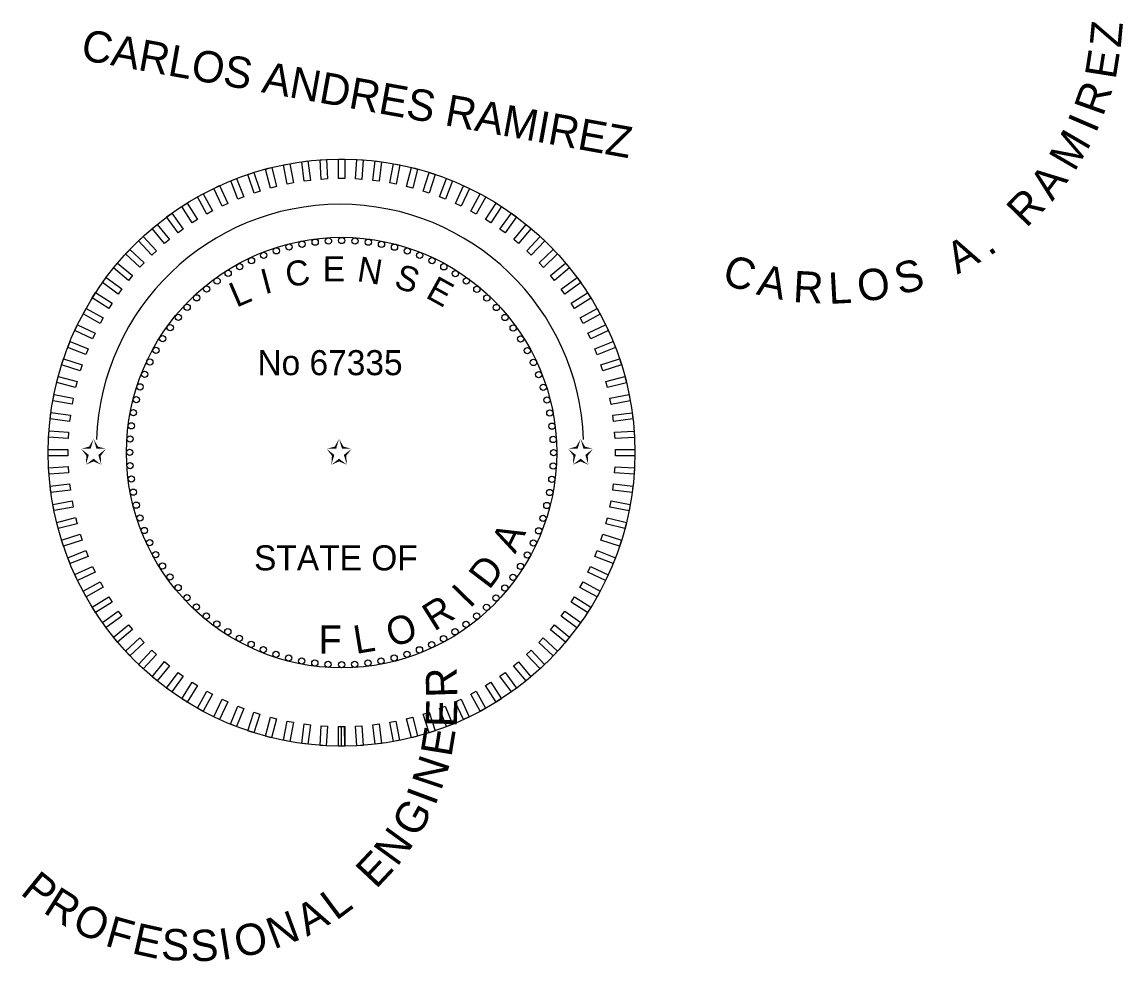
# Model space of a CAD drawing. Extents: x -0.86 to 1.33, y -1.26 to 1.83.
# Drawn here: x -0.5531 to -0.2599, y 0.6499 to 0.9 of the extents above; entities that cross this region are included whole.
import ezdxf

# ---------------------------------------------------------------- set-up
doc = ezdxf.new("R2010")
doc.units = 0
for name, color, linetype in [('Default', 7, 'Continuous'), ('FLMap1', 7, 'Continuous'), ('FLMap3', 7, 'Continuous'), ('TextMisc', 7, 'Continuous')]:
    doc.layers.add(name, color=color, linetype=linetype)

msp = doc.modelspace()

# ---------------------------------------------------------------- linework, layer by layer
at = {"layer": 'Default'}
msp.add_arc((-0.46841, 0.78662), 0.06487, 2.0456, 177.9544, dxfattribs=at)
at = {"layer": 'FLMap1'}
for radius in [0.07809, 0.05727]:
    msp.add_circle((-0.46797, 0.78544), radius, dxfattribs=at)
at = {"layer": 'FLMap3'}
for p, q in [((-0.46881, 0.70734), (-0.46882, 0.71255)), ((-0.46797, 0.70734), (-0.46799, 0.71255)), ((-0.46714, 0.70735), (-0.46716, 0.71255))]:
    msp.add_line(p, q, dxfattribs=at)
for points in [[(-0.4808, 0.8572), (-0.48245, 0.85688), (-0.48342, 0.86199), (-0.48177, 0.8623)], [(-0.47627, 0.85786), (-0.47794, 0.85765), (-0.47859, 0.86281), (-0.47692, 0.86302)], [(-0.4717, 0.85824), (-0.47338, 0.85813), (-0.47371, 0.86332), (-0.47203, 0.86343)], [(-0.46713, 0.85833), (-0.46881, 0.85833), (-0.46881, 0.86353), (-0.46713, 0.86353)], [(-0.46255, 0.85813), (-0.46423, 0.85824), (-0.4639, 0.86343), (-0.46222, 0.86332)], [(-0.458, 0.85765), (-0.45966, 0.85786), (-0.45901, 0.86302), (-0.45734, 0.86281)], [(-0.45348, 0.85688), (-0.45513, 0.85719), (-0.45416, 0.8623), (-0.45251, 0.86199)], [(-0.48969, 0.85502), (-0.49129, 0.8545), (-0.4929, 0.85945), (-0.4913, 0.85997)], [(-0.48528, 0.85625), (-0.48691, 0.85583), (-0.4882, 0.86087), (-0.48657, 0.86129)], [(-0.44902, 0.85583), (-0.45065, 0.85624), (-0.44936, 0.86128), (-0.44773, 0.86086)], [(-0.44464, 0.8545), (-0.44624, 0.85502), (-0.44463, 0.85996), (-0.44304, 0.85944)], [(-0.49824, 0.85175), (-0.49976, 0.85104), (-0.50198, 0.85574), (-0.50046, 0.85646)], [(-0.49402, 0.85352), (-0.49558, 0.8529), (-0.4975, 0.85774), (-0.49593, 0.85836)], [(-0.44035, 0.8529), (-0.44192, 0.85352), (-0.44, 0.85835), (-0.43844, 0.85773)], [(-0.43617, 0.85103), (-0.43769, 0.85175), (-0.43548, 0.85645), (-0.43396, 0.85574)], [(-0.50235, 0.84972), (-0.50382, 0.84891), (-0.50632, 0.85347), (-0.50485, 0.85428)], [(-0.43211, 0.8489), (-0.43359, 0.84971), (-0.43108, 0.85427), (-0.42961, 0.85346)], [(-0.50631, 0.84744), (-0.50773, 0.84653), (-0.51052, 0.85093), (-0.5091, 0.85183)], [(-0.4282, 0.84653), (-0.42962, 0.84743), (-0.42683, 0.85182), (-0.42541, 0.85092)], [(-0.51013, 0.84491), (-0.51149, 0.84392), (-0.51455, 0.84813), (-0.51319, 0.84911)], [(-0.42444, 0.84391), (-0.4258, 0.8449), (-0.42275, 0.8491), (-0.42139, 0.84812)], [(-0.51378, 0.84214), (-0.51508, 0.84107), (-0.51839, 0.84508), (-0.5171, 0.84615)], [(-0.42086, 0.84106), (-0.42215, 0.84213), (-0.41884, 0.84614), (-0.41754, 0.84507)], [(-0.51725, 0.83915), (-0.51848, 0.838), (-0.52204, 0.84179), (-0.52081, 0.84294)], [(-0.41746, 0.83799), (-0.41868, 0.83914), (-0.41512, 0.84293), (-0.4139, 0.84178)], [(-0.52053, 0.83595), (-0.52168, 0.83473), (-0.52547, 0.83829), (-0.52432, 0.83951)], [(-0.41426, 0.83472), (-0.41541, 0.83594), (-0.41162, 0.8395), (-0.41047, 0.83828)], [(-0.5236, 0.83255), (-0.52467, 0.83126), (-0.52867, 0.83457), (-0.5276, 0.83587)], [(-0.41127, 0.83125), (-0.41234, 0.83254), (-0.40833, 0.83586), (-0.40726, 0.83456)], [(-0.52644, 0.82897), (-0.52743, 0.82761), (-0.53164, 0.83066), (-0.53065, 0.83202)], [(-0.40851, 0.82759), (-0.40949, 0.82896), (-0.40529, 0.83201), (-0.4043, 0.83065)], [(-0.52906, 0.82521), (-0.52996, 0.82379), (-0.53435, 0.82658), (-0.53345, 0.828)], [(-0.40598, 0.82378), (-0.40688, 0.8252), (-0.40249, 0.82798), (-0.40158, 0.82656)], [(-0.53144, 0.8213), (-0.53225, 0.81982), (-0.53681, 0.82233), (-0.536, 0.8238)], [(-0.40369, 0.81981), (-0.4045, 0.82128), (-0.39994, 0.82379), (-0.39913, 0.82231)], [(-0.53357, 0.81724), (-0.53428, 0.81572), (-0.53899, 0.81793), (-0.53827, 0.81946)], [(-0.40166, 0.8157), (-0.40238, 0.81723), (-0.39767, 0.81944), (-0.39695, 0.81792)], [(-0.53543, 0.81306), (-0.53605, 0.8115), (-0.54089, 0.81341), (-0.54027, 0.81497)], [(-0.39989, 0.81148), (-0.40051, 0.81304), (-0.39567, 0.81496), (-0.39505, 0.8134)], [(-0.53703, 0.80877), (-0.53755, 0.80717), (-0.5425, 0.80878), (-0.54198, 0.81038)], [(-0.39839, 0.80715), (-0.39891, 0.80875), (-0.39396, 0.81036), (-0.39344, 0.80876)], [(-0.53836, 0.80439), (-0.53878, 0.80276), (-0.54382, 0.80405), (-0.5434, 0.80568)], [(-0.39716, 0.80274), (-0.39758, 0.80437), (-0.39254, 0.80566), (-0.39212, 0.80404)], [(-0.53941, 0.79993), (-0.53973, 0.79828), (-0.54484, 0.79925), (-0.54452, 0.8009)], [(-0.39622, 0.79826), (-0.39653, 0.79991), (-0.39142, 0.80089), (-0.39111, 0.79924)], [(-0.54018, 0.79541), (-0.54039, 0.79375), (-0.54555, 0.7944), (-0.54534, 0.79607)], [(-0.39555, 0.79373), (-0.39576, 0.7954), (-0.3906, 0.79605), (-0.39039, 0.79438)], [(-0.54067, 0.79086), (-0.54077, 0.78918), (-0.54596, 0.78951), (-0.54586, 0.79119)], [(-0.39517, 0.78917), (-0.39528, 0.79085), (-0.39009, 0.79117), (-0.38998, 0.78949)], [(-0.54086, 0.78629), (-0.54086, 0.7846), (-0.54606, 0.7846), (-0.54606, 0.78629)], [(-0.39508, 0.78459), (-0.39508, 0.78627), (-0.38988, 0.78627), (-0.38988, 0.78459)], [(-0.54077, 0.78171), (-0.54067, 0.78003), (-0.54586, 0.7797), (-0.54596, 0.78138)], [(-0.39528, 0.78001), (-0.39518, 0.78169), (-0.38998, 0.78137), (-0.39009, 0.77969)], [(-0.5404, 0.77714), (-0.54018, 0.77548), (-0.54534, 0.77482), (-0.54556, 0.77649)], [(-0.39576, 0.77546), (-0.39555, 0.77713), (-0.39039, 0.77648), (-0.3906, 0.77481)], [(-0.53973, 0.77261), (-0.53942, 0.77096), (-0.54453, 0.76999), (-0.54484, 0.77164)], [(-0.39653, 0.77095), (-0.39622, 0.7726), (-0.39111, 0.77162), (-0.39142, 0.76997)], [(-0.53878, 0.76813), (-0.53837, 0.7665), (-0.5434, 0.76521), (-0.54382, 0.76684)], [(-0.39758, 0.76649), (-0.39717, 0.76812), (-0.39213, 0.76682), (-0.39255, 0.7652)], [(-0.53756, 0.76372), (-0.53704, 0.76212), (-0.54199, 0.76051), (-0.5425, 0.76211)], [(-0.39891, 0.76211), (-0.39839, 0.76371), (-0.39345, 0.7621), (-0.39397, 0.7605)], [(-0.53606, 0.75939), (-0.53544, 0.75783), (-0.54027, 0.75592), (-0.54089, 0.75748)], [(-0.40051, 0.75782), (-0.3999, 0.75938), (-0.39506, 0.75746), (-0.39568, 0.7559)], [(-0.53429, 0.75517), (-0.53357, 0.75365), (-0.53828, 0.75143), (-0.53899, 0.75296)], [(-0.40238, 0.75363), (-0.40167, 0.75516), (-0.39696, 0.75294), (-0.39768, 0.75142)], [(-0.53226, 0.75107), (-0.53145, 0.74959), (-0.536, 0.74709), (-0.53681, 0.74856)], [(-0.40451, 0.74958), (-0.4037, 0.75105), (-0.39914, 0.74855), (-0.39995, 0.74707)], [(-0.52997, 0.7471), (-0.52907, 0.74568), (-0.53346, 0.74289), (-0.53436, 0.74431)], [(-0.40689, 0.74566), (-0.40598, 0.74708), (-0.40159, 0.7443), (-0.40249, 0.74288)], [(-0.52744, 0.74328), (-0.52645, 0.74192), (-0.53066, 0.73886), (-0.53165, 0.74022)], [(-0.4095, 0.74191), (-0.40851, 0.74327), (-0.40431, 0.74021), (-0.4053, 0.73885)], [(-0.52468, 0.73963), (-0.52361, 0.73833), (-0.52761, 0.73502), (-0.52868, 0.73631)], [(-0.41235, 0.73832), (-0.41128, 0.73962), (-0.40727, 0.7363), (-0.40834, 0.73501)], [(-0.52169, 0.73616), (-0.52054, 0.73493), (-0.52433, 0.73137), (-0.52548, 0.7326)], [(-0.41542, 0.73492), (-0.41427, 0.73615), (-0.41048, 0.73259), (-0.41163, 0.73136)], [(-0.51849, 0.73288), (-0.51726, 0.73173), (-0.52082, 0.72794), (-0.52205, 0.72909)], [(-0.4187, 0.73172), (-0.41747, 0.73287), (-0.41391, 0.72908), (-0.41513, 0.72793)], [(-0.51509, 0.72982), (-0.51379, 0.72874), (-0.51711, 0.72474), (-0.5184, 0.72581)], [(-0.5115, 0.72697), (-0.51014, 0.72598), (-0.5132, 0.72177), (-0.51456, 0.72276)], [(-0.42582, 0.72597), (-0.42446, 0.72696), (-0.4214, 0.72275), (-0.42276, 0.72176)], [(-0.42217, 0.72873), (-0.42087, 0.72981), (-0.41755, 0.7258), (-0.41885, 0.72473)], [(-0.50775, 0.72435), (-0.50633, 0.72345), (-0.50911, 0.71906), (-0.51053, 0.71996)], [(-0.42963, 0.72344), (-0.42821, 0.72434), (-0.42543, 0.71995), (-0.42685, 0.71905)], [(-0.50383, 0.72197), (-0.50236, 0.72116), (-0.50486, 0.7166), (-0.50634, 0.71741)], [(-0.4336, 0.72115), (-0.43213, 0.72196), (-0.42962, 0.71741), (-0.4311, 0.7166)], [(-0.49978, 0.71985), (-0.49825, 0.71913), (-0.50047, 0.71442), (-0.50199, 0.71514)], [(-0.43771, 0.71912), (-0.43618, 0.71984), (-0.43397, 0.71513), (-0.43549, 0.71442)], [(-0.4956, 0.71798), (-0.49403, 0.71736), (-0.49595, 0.71252), (-0.49751, 0.71314)], [(-0.4913, 0.71638), (-0.48971, 0.71586), (-0.49131, 0.71091), (-0.49291, 0.71143)], [(-0.44626, 0.71585), (-0.44466, 0.71637), (-0.44305, 0.71143), (-0.44465, 0.71091)], [(-0.44193, 0.71735), (-0.44037, 0.71797), (-0.43845, 0.71314), (-0.44002, 0.71252)], [(-0.48692, 0.71505), (-0.48529, 0.71463), (-0.48659, 0.70959), (-0.48822, 0.71001)], [(-0.48247, 0.714), (-0.48081, 0.71368), (-0.48179, 0.70857), (-0.48344, 0.70889)], [(-0.47795, 0.71323), (-0.47628, 0.71302), (-0.47693, 0.70786), (-0.4786, 0.70807)], [(-0.4734, 0.71274), (-0.47172, 0.71264), (-0.47205, 0.70745), (-0.47372, 0.70755)], [(-0.46882, 0.71255), (-0.46714, 0.71255), (-0.46714, 0.70735), (-0.46882, 0.70735)], [(-0.46424, 0.71264), (-0.46257, 0.71274), (-0.46224, 0.70755), (-0.46392, 0.70745)], [(-0.45968, 0.71302), (-0.45801, 0.71323), (-0.45736, 0.70807), (-0.45903, 0.70786)], [(-0.45515, 0.71368), (-0.4535, 0.71399), (-0.45252, 0.70889), (-0.45417, 0.70857)], [(-0.45067, 0.71463), (-0.44904, 0.71504), (-0.44775, 0.71001), (-0.44937, 0.70959)]]:
    msp.add_lwpolyline(points, close=True, dxfattribs=at)
for centre in [(-0.4785, 0.84088), (-0.475, 0.84143), (-0.47147, 0.84176), (-0.46793, 0.84187), (-0.46438, 0.84176), (-0.46085, 0.84142), (-0.45735, 0.84086), (-0.4887, 0.83793), (-0.48537, 0.83912), (-0.48196, 0.84011), (-0.45389, 0.84009), (-0.45049, 0.83909), (-0.44716, 0.83789), (-0.49512, 0.83491), (-0.49196, 0.83652), (-0.4439, 0.83648), (-0.44075, 0.83487), (-0.49817, 0.83311), (-0.4377, 0.83306), (-0.50391, 0.82895), (-0.50111, 0.83112), (-0.43477, 0.83107), (-0.43197, 0.82889), (-0.50657, 0.82661), (-0.42931, 0.82654), (-0.50908, 0.8241), (-0.4268, 0.82403), (-0.51143, 0.82145), (-0.42446, 0.82137), (-0.5136, 0.81865), (-0.42229, 0.81857), (-0.5156, 0.81572), (-0.4203, 0.81564), (-0.5174, 0.81267), (-0.4185, 0.81258), (-0.51902, 0.80951), (-0.41689, 0.80942), (-0.52043, 0.80626), (-0.41549, 0.80617), (-0.52163, 0.80292), (-0.41429, 0.80283), (-0.52262, 0.79952), (-0.4133, 0.79943), (-0.5234, 0.79606), (-0.41253, 0.79597), (-0.52396, 0.79256), (-0.41198, 0.79246), (-0.52429, 0.78903), (-0.41165, 0.78893), (-0.52441, 0.78548), (-0.41154, 0.78539), (-0.5243, 0.78194), (-0.41165, 0.78185), (-0.52397, 0.77841), (-0.41199, 0.77832), (-0.52342, 0.77491), (-0.41255, 0.77482), (-0.52265, 0.77145), (-0.41333, 0.77136), (-0.52166, 0.76804), (-0.41432, 0.76795), (-0.52046, 0.76471), (-0.41552, 0.76462), (-0.51906, 0.76145), (-0.41693, 0.76137), (-0.51745, 0.75829), (-0.41854, 0.75821), (-0.51565, 0.75524), (-0.42035, 0.75516), (-0.51366, 0.75231), (-0.42235, 0.75223), (-0.51149, 0.7495), (-0.50914, 0.74684), (-0.42687, 0.74677), (-0.42452, 0.74943), (-0.50664, 0.74433), (-0.42938, 0.74427), (-0.50398, 0.74199), (-0.43204, 0.74193), (-0.50118, 0.73981), (-0.49825, 0.73781), (-0.43484, 0.73975), (-0.4952, 0.73601), (-0.44083, 0.73596), (-0.43777, 0.73776), (-0.49204, 0.7344), (-0.48879, 0.73298), (-0.44724, 0.73295), (-0.44399, 0.73436), (-0.48546, 0.73178), (-0.48205, 0.73079), (-0.47859, 0.73001), (-0.47509, 0.72946), (-0.47156, 0.72912), (-0.46448, 0.72911), (-0.46095, 0.72944), (-0.45745, 0.73), (-0.45398, 0.73077), (-0.45058, 0.73175), (-0.46797, 0.729)]:
    msp.add_circle(centre, 0.000833, dxfattribs=at)

# ---------------------------------------------------------------- texts
for s, rotation, p in [('C', 8.9826, (-0.48238, 0.82941)), ('E', 359.9662, (-0.47299, 0.83099)), ('N', 350.6464, (-0.46409, 0.8311)), ('I', 14.8189, (-0.48843, 0.82752)), ('S', 341.04, (-0.45433, 0.82954)), ('L', 23.3052, (-0.49598, 0.82395)), ('E', 331.1686, (-0.44588, 0.82682))]:
    msp.add_text(s, height=0.00666, rotation=rotation, dxfattribs=at).set_placement(p)
for p in [(-0.53753, 0.78228), (-0.47216, 0.78228), (-0.40787, 0.78228)]:
    msp.add_text('✩', height=0.00666, dxfattribs=at).set_placement(p)
at = {"layer": 'TextMisc'}
for s, height, rotation, p in [('Z', 0.00833, 84.6298, (-0.26055, 0.89304)), ('CARLOS ANDRES RAMIREZ', 0.00833, 349.8111, (-0.53766, 0.89)), ('E', 0.00833, 81.0526, (-0.26191, 0.88452)), ('R', 0.00833, 70.354, (-0.2653, 0.87463)), ('I', 0.00833, 66.8045, (-0.26721, 0.87016)), ('M', 0.00833, 59.7405, (-0.27286, 0.85992)), ('A', 0.00833, 52.7338, (-0.27877, 0.85209)), ('R', 0.00833, 45.7967, (-0.28567, 0.84501)), ('A', 0.00833, 28.8314, (-0.30404, 0.83275)), ('.', 0.00833, 35.5463, (-0.29555, 0.83755)), ('C', 0.00833, 342.3164, (-0.36704, 0.83048)), ('S', 0.00833, 15.7273, (-0.3194, 0.8273)), ('A', 0.00833, 348.0816, (-0.35781, 0.82755)), ('R', 0.00833, 356.9939, (-0.34792, 0.82551)), ('L', 0.00833, 3.1074, (-0.33817, 0.82497)), ('O', 0.00833, 9.3536, (-0.32999, 0.82537)), ('A', 0.0075, 63.2661, (-0.42175, 0.7583)), ('D', 0.0075, 52.7338, (-0.42869, 0.74872)), ('I', 0.0075, 45.7967, (-0.43386, 0.74379)), ('R', 0.0075, 32.1761, (-0.44333, 0.73774)), ('O', 0.0075, 18.96, (-0.45456, 0.73348)), ('F', 0.0075, 0.0338, (-0.47407, 0.73194)), ('L', 0.0075, 9.3536, (-0.46416, 0.73185)), ('R', 0.00833, 91.8188, (-0.4371, 0.72035)), ('E', 0.00833, 88.1812, (-0.43733, 0.71225)), ('E', 0.00833, 80.6737, (-0.43876, 0.70425)), ('N', 0.00833, 71.6619, (-0.44152, 0.69526)), ('I', 0.00833, 69.57, (-0.44309, 0.69121)), ('G', 0.00833, 60.8746, (-0.44773, 0.68267)), ('N', 0.00833, 53.9986, (-0.45321, 0.67503)), ('E', 0.00833, 46.8094, (-0.45881, 0.66914)), ('P', 0.00833, 321.0594, (-0.55376, 0.66815)), ('R', 0.00833, 327.8239, (-0.54773, 0.66322)), ('L', 0.00833, 36.7249, (-0.46945, 0.66076)), ('A', 0.00833, 28.7821, (-0.4772, 0.65659)), ('O', 0.00833, 334.487, (-0.54019, 0.65853)), ('N', 0.00833, 20.5125, (-0.48599, 0.65322)), ('F', 0.00833, 344.2727, (-0.53127, 0.65431)), ('E', 0.00833, 347.4752, (-0.52408, 0.65228)), ('O', 0.00833, 11.9184, (-0.49557, 0.65098)), ('S', 0.00833, 356.8926, (-0.51614, 0.65055)), ('S', 0.00833, 3.0061, (-0.50801, 0.64998)), ('I', 0.00833, 8.9826, (-0.49988, 0.65038))]:
    msp.add_text(s, height=height, rotation=rotation, dxfattribs=at).set_placement(p)
for s, p in [('No 67335', (-0.49038, 0.80603)), ('STATE OF', (-0.49127, 0.7541))]:
    msp.add_text(s, height=0.006664, dxfattribs=at).set_placement(p)

doc.saveas('drawing.dxf')
